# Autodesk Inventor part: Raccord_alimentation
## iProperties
Created: 2011-01
Part Number: Raccord_alimentation
Document SubType Name: Modeling
Designer: eric
Density: 1 g/cm^3
Mass: 36.0619 g
Surface Area: 95.5468 cm^2
Volume: 36.0619 cm^3
Author: eric
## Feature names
1. Base1
